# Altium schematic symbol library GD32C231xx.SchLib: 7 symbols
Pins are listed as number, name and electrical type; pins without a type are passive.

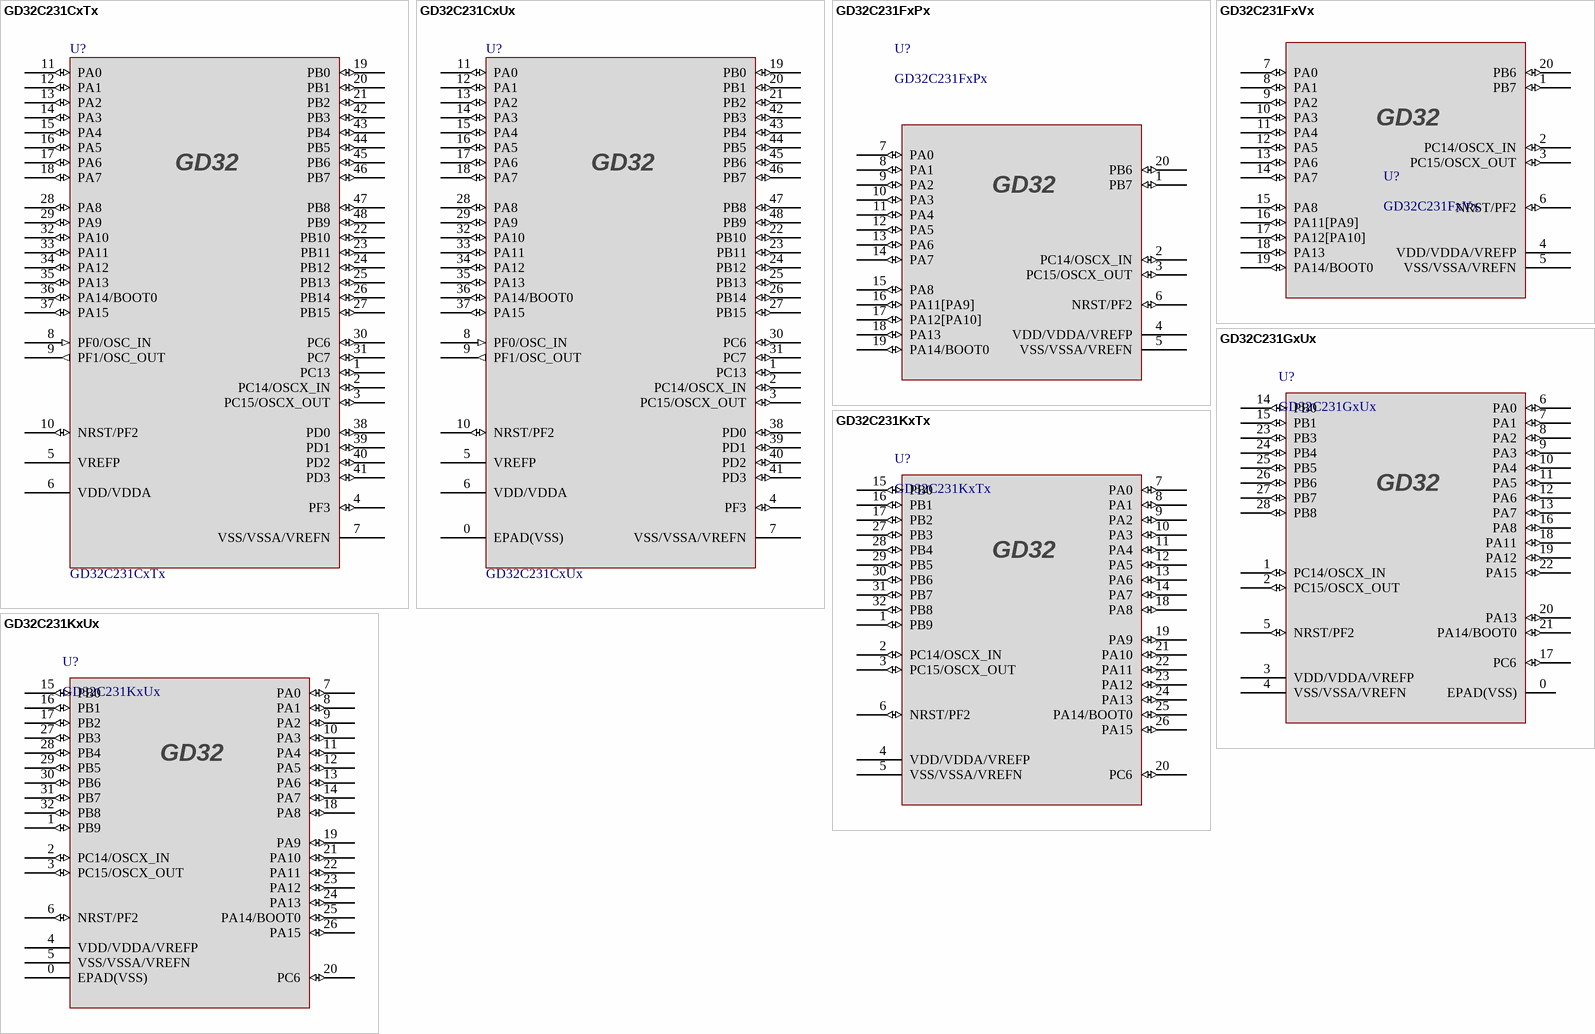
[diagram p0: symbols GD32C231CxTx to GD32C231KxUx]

## GD32C231CxTx
designator U?
footprint LQFP48_7x7x1.6
pins: 1 PC13 (io), 2 PC14/OSCX_IN (io), 3 PC15/OSCX_OUT (io), 4 PF3 (io), 5 VREFP (power), 6 VDD/VDDA (power), 7 VSS/VSSA/VREFN (power), 8 PF0/OSC_IN (in), 9 PF1/OSC_OUT (out), 10 NRST/PF2 (io), 11 PA0 (io), 12 PA1 (io), 13 PA2 (io), 14 PA3 (io), 15 PA4 (io), 16 PA5 (io), 17 PA6 (io), 18 PA7 (io), 19 PB0 (io), 20 PB1 (io), 21 PB2 (io), 22 PB10 (io), 23 PB11 (io), 24 PB12 (io), 25 PB13 (io), 26 PB14 (io), 27 PB15 (io), 28 PA8 (io), 29 PA9 (io), 30 PC6 (io), 31 PC7 (io), 32 PA10 (io), 33 PA11 (io), 34 PA12 (io), 35 PA13 (io), 36 PA14/BOOT0 (io), 37 PA15 (io), 38 PD0 (io), 39 PD1 (io), 40 PD2 (io), 41 PD3 (io), 42 PB3 (io), 43 PB4 (io), 44 PB5 (io), 45 PB6 (io), 46 PB7 (io), 47 PB8 (io), 48 PB9 (io)
2 alternate drawings of the same symbol

## GD32C231CxUx
designator U?
footprint QFN48_7X7X0.6
pins: 0 EPAD(VSS) (power), 1 PC13 (io), 2 PC14/OSCX_IN (io), 3 PC15/OSCX_OUT (io), 4 PF3 (io), 5 VREFP (power), 6 VDD/VDDA (power), 7 VSS/VSSA/VREFN (power), 8 PF0/OSC_IN (in), 9 PF1/OSC_OUT (out), 10 NRST/PF2 (io), 11 PA0 (io), 12 PA1 (io), 13 PA2 (io), 14 PA3 (io), 15 PA4 (io), 16 PA5 (io), 17 PA6 (io), 18 PA7 (io), 19 PB0 (io), 20 PB1 (io), 21 PB2 (io), 22 PB10 (io), 23 PB11 (io), 24 PB12 (io), 25 PB13 (io), 26 PB14 (io), 27 PB15 (io), 28 PA8 (io), 29 PA9 (io), 30 PC6 (io), 31 PC7 (io), 32 PA10 (io), 33 PA11 (io), 34 PA12 (io), 35 PA13 (io), 36 PA14/BOOT0 (io), 37 PA15 (io), 38 PD0 (io), 39 PD1 (io), 40 PD2 (io), 41 PD3 (io), 42 PB3 (io), 43 PB4 (io), 44 PB5 (io), 45 PB6 (io), 46 PB7 (io), 47 PB8 (io), 48 PB9 (io)
2 alternate drawings of the same symbol

## GD32C231FxPx
designator U?
footprint TSSOP20-4.5x6.6x1.2
pins: 1 PB7 (io), 2 PC14/OSCX_IN (io), 3 PC15/OSCX_OUT (io), 4 VDD/VDDA/VREFP (power), 5 VSS/VSSA/VREFN (power), 6 NRST/PF2 (io), 7 PA0 (io), 8 PA1 (io), 9 PA2 (io), 10 PA3 (io), 11 PA4 (io), 12 PA5 (io), 13 PA6 (io), 14 PA7 (io), 15 PA8 (io), 16 PA11[PA9] (io), 17 PA12[PA10] (io), 18 PA13 (io), 19 PA14/BOOT0 (io), 20 PB6 (io)

## GD32C231FxVx
designator U?
footprint LGA20_3x3X0.61
pins: 1 PB7 (io), 2 PC14/OSCX_IN (io), 3 PC15/OSCX_OUT (io), 4 VDD/VDDA/VREFP (power), 5 VSS/VSSA/VREFN (power), 6 NRST/PF2 (io), 7 PA0 (io), 8 PA1 (io), 9 PA2 (io), 10 PA3 (io), 11 PA4 (io), 12 PA5 (io), 13 PA6 (io), 14 PA7 (io), 15 PA8 (io), 16 PA11[PA9] (io), 17 PA12[PA10] (io), 18 PA13 (io), 19 PA14/BOOT0 (io), 20 PB6 (io)

## GD32C231GxUx
designator U?
footprint QFN28_4X4X0.60
pins: 0 EPAD(VSS) (power), 1 PC14/OSCX_IN (io), 2 PC15/OSCX_OUT (io), 3 VDD/VDDA/VREFP (power), 4 VSS/VSSA/VREFN (power), 5 NRST/PF2 (io), 6 PA0 (io), 7 PA1 (io), 8 PA2 (io), 9 PA3 (io), 10 PA4 (io), 11 PA5 (io), 12 PA6 (io), 13 PA7 (io), 14 PB0 (io), 15 PB1 (io), 16 PA8 (io), 17 PC6 (io), 18 PA11 (io), 19 PA12 (io), 20 PA13 (io), 21 PA14/BOOT0 (io), 22 PA15 (io), 23 PB3 (io), 24 PB4 (io), 25 PB5 (io), 26 PB6 (io), 27 PB7 (io), 28 PB8 (io)

## GD32C231KxTx
designator U?
footprint LQFP32_7x7X1.6
pins: 1 PB9 (io), 2 PC14/OSCX_IN (io), 3 PC15/OSCX_OUT (io), 4 VDD/VDDA/VREFP (power), 5 VSS/VSSA/VREFN (power), 6 NRST/PF2 (io), 7 PA0 (io), 8 PA1 (io), 9 PA2 (io), 10 PA3 (io), 11 PA4 (io), 12 PA5 (io), 13 PA6 (io), 14 PA7 (io), 15 PB0 (io), 16 PB1 (io), 17 PB2 (io), 18 PA8 (io), 19 PA9 (io), 20 PC6 (io), 21 PA10 (io), 22 PA11 (io), 23 PA12 (io), 24 PA13 (io), 25 PA14/BOOT0 (io), 26 PA15 (io), 27 PB3 (io), 28 PB4 (io), 29 PB5 (io), 30 PB6 (io), 31 PB7 (io), 32 PB8 (io)

## GD32C231KxUx
designator U?
footprint QFN32_5X5X0.6
pins: 0 EPAD(VSS) (power), 1 PB9 (io), 2 PC14/OSCX_IN (io), 3 PC15/OSCX_OUT (io), 4 VDD/VDDA/VREFP (power), 5 VSS/VSSA/VREFN (power), 6 NRST/PF2 (io), 7 PA0 (io), 8 PA1 (io), 9 PA2 (io), 10 PA3 (io), 11 PA4 (io), 12 PA5 (io), 13 PA6 (io), 14 PA7 (io), 15 PB0 (io), 16 PB1 (io), 17 PB2 (io), 18 PA8 (io), 19 PA9 (io), 20 PC6 (io), 21 PA10 (io), 22 PA11 (io), 23 PA12 (io), 24 PA13 (io), 25 PA14/BOOT0 (io), 26 PA15 (io), 27 PB3 (io), 28 PB4 (io), 29 PB5 (io), 30 PB6 (io), 31 PB7 (io), 32 PB8 (io)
